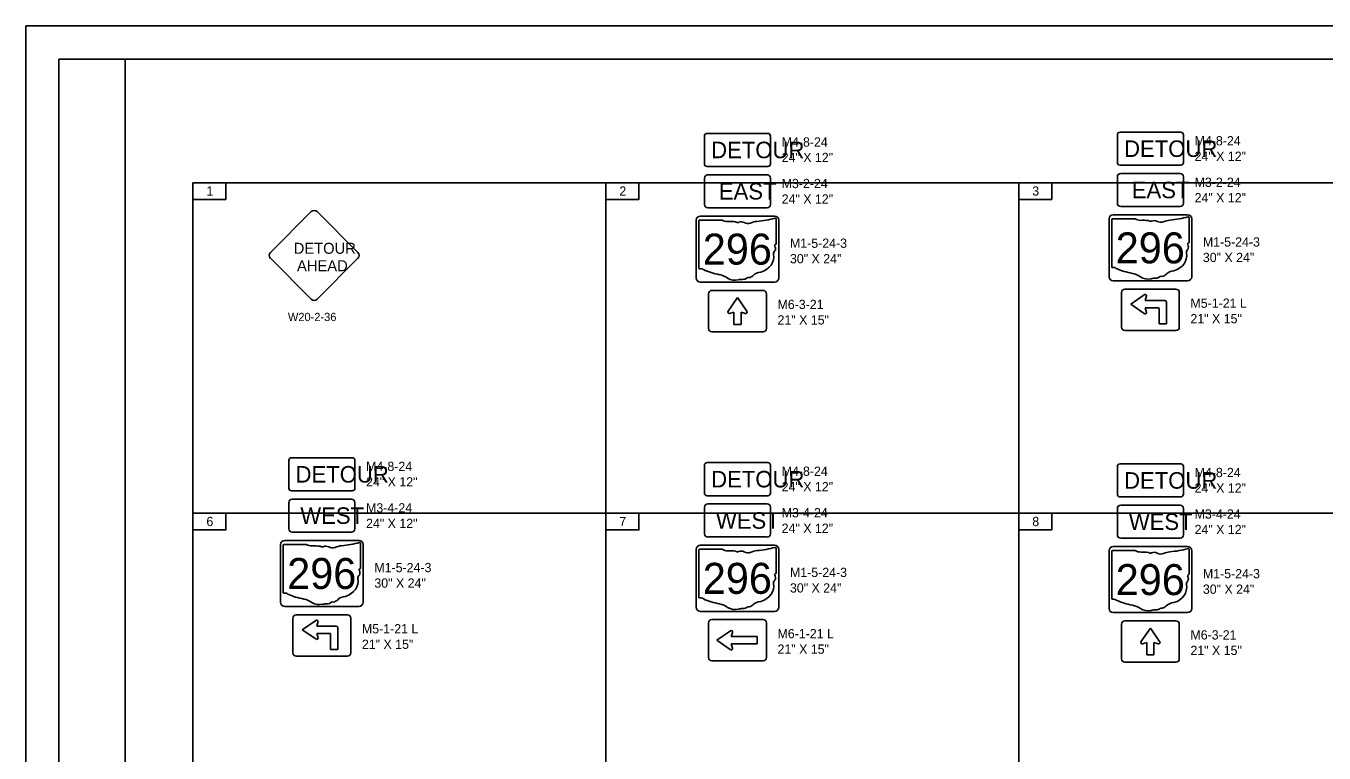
# Model space of a CAD drawing. Extents: x 0 to 715, y 0 to 440.
# Drawn here: x 0 to 393, y 220 to 440 of the extents above; entities that cross this region are included whole.
import ezdxf

# ---------------------------------------------------------------- set-up
doc = ezdxf.new("R2010")
doc.units = 0
for name, color, linetype in [('SC_Scratch1', 7, 'Continuous'), ('SH_Border', 7, 'Continuous'), ('SH_Cut_Line', 7, 'Continuous'), ('SH_Text', 7, 'Continuous'), ('SN_P_Signs', 7, 'Continuous'), ('SN_P_Text', 7, 'Continuous')]:
    doc.layers.add(name, color=color, linetype=linetype)

msp = doc.modelspace()

# ---------------------------------------------------------------- linework, layer by layer
at = {"layer": 'SC_Scratch1'}
for p, q in [((50.54, 392.53), (50.54, 292.53)), ((50.54, 392.53), (225.54, 392.53)), ((175.54, 392.53), (175.54, 292.53)), ((225.54, 392.53), (375.54, 392.53)), ((300.54, 392.53), (300.54, 292.53)), ((375.54, 392.53), (550.54, 392.53)), ((50.54, 292.53), (50.54, 192.53)), ((50.54, 292.53), (225.54, 292.53)), ((175.54, 292.53), (175.54, 192.53)), ((225.54, 292.53), (375.54, 292.53)), ((300.54, 292.53), (300.54, 192.53)), ((375.54, 292.53), (550.54, 292.53))]:
    msp.add_line(p, q, dxfattribs=at)
at = {"layer": 'SH_Border'}
for points in [[(10, 430), (30, 430), (30, 10), (10, 10)], [(30, 430), (670, 430), (670, 10), (30, 10)]]:
    msp.add_lwpolyline(points, close=True, dxfattribs=at)
at = {"layer": 'SH_Cut_Line'}
msp.add_lwpolyline([(0, 0), (680, 0), (680, 440), (0, 440)], close=True, dxfattribs=at)
at = {"layer": 'SH_Text'}
for points in [[(50.54, 392.53), (60.54, 392.53), (60.54, 387.53), (50.54, 387.53)], [(175.54, 392.53), (185.54, 392.53), (185.54, 387.53), (175.54, 387.53)], [(300.54, 392.53), (310.54, 392.53), (310.54, 387.53), (300.54, 387.53)], [(50.54, 292.53), (60.54, 292.53), (60.54, 287.53), (50.54, 287.53)], [(175.54, 292.53), (185.54, 292.53), (185.54, 287.53), (175.54, 287.53)], [(300.54, 292.53), (310.54, 292.53), (310.54, 287.53), (300.54, 287.53)]]:
    msp.add_lwpolyline(points, close=True, dxfattribs=at)
at = {"layer": 'SN_P_Signs'}
for p, q in [((205.39, 385.99), (205.39, 393.99)), ((206.39, 394.99), (224.39, 394.99)), ((225.39, 393.99), (225.39, 385.99)), ((330.39, 386.37), (330.39, 394.37)), ((331.39, 395.37), (349.39, 395.37)), ((350.39, 394.37), (350.39, 386.37)), ((349.39, 385.37), (331.39, 385.37)), ((210.76, 381.26), (203.9, 381.26)), ((224.39, 384.99), (206.39, 384.99)), ((227.11, 374.17), (227.11, 381.61)), ((328.67, 381.39), (328.67, 367.16)), ((335.76, 381.64), (328.9, 381.64)), ((352.11, 374.55), (352.11, 381.99)), ((203.67, 381.02), (203.67, 366.79)), ((227.1, 374.17), (227.11, 374.17)), ((352.1, 374.55), (352.11, 374.55)), ((206.64, 348.49), (206.64, 358.99)), ((207.64, 359.99), (223.14, 359.99)), ((212.54, 353.66), (215.39, 357.8)), ((215.39, 357.8), (218.18, 353.72)), ((224.14, 358.99), (224.14, 348.49)), ((331.64, 348.87), (331.64, 359.37)), ((332.64, 360.37), (348.14, 360.37)), ((338.53, 358.63), (334.45, 355.83)), ((338.83, 356.93), (339.24, 358.33)), ((349.14, 359.37), (349.14, 348.87)), ((334.45, 355.83), (338.53, 353.04)), ((344.76, 356.93), (338.83, 356.93)), ((339.24, 353.33), (338.83, 354.74)), ((338.83, 354.74), (342.73, 354.74)), ((343.04, 354.43), (343.04, 349.9)), ((344.76, 356.93), (344.76, 356.93)), ((345.23, 349.9), (345.23, 356.46)), ((214.29, 353.42), (213.01, 353.03)), ((214.29, 349.67), (214.29, 353.42)), ((217.76, 353.03), (216.48, 353.42)), ((216.48, 353.42), (216.48, 349.67)), ((343.04, 349.9), (345.23, 349.9)), ((343.04, 349.9), (345.23, 349.9)), ((223.14, 347.49), (207.64, 347.49)), ((216.48, 349.67), (214.29, 349.67)), ((348.14, 347.87), (332.64, 347.87)), ((79.58, 287.84), (79.58, 295.84)), ((80.58, 296.84), (98.58, 296.84)), ((99.58, 295.84), (99.58, 287.84)), ((206.39, 295.37), (224.39, 295.37)), ((331.39, 294.99), (349.39, 294.99)), ((205.39, 286.37), (205.39, 294.37)), ((225.39, 294.37), (225.39, 286.37)), ((330.39, 285.99), (330.39, 293.99)), ((350.39, 293.99), (350.39, 285.99)), ((84.95, 283.11), (78.09, 283.11)), ((98.58, 286.84), (80.58, 286.84)), ((101.29, 276.02), (101.29, 283.46)), ((224.39, 285.37), (206.39, 285.37)), ((349.39, 284.99), (331.39, 284.99)), ((77.86, 282.87), (77.86, 268.64)), ((203.67, 281.39), (203.67, 267.16)), ((210.76, 281.64), (203.9, 281.64)), ((227.11, 274.55), (227.11, 281.99)), ((328.67, 281.02), (328.67, 266.79)), ((335.76, 281.26), (328.9, 281.26)), ((352.11, 274.17), (352.11, 281.61)), ((101.29, 276.02), (101.29, 276.02)), ((227.1, 274.55), (227.11, 274.55)), ((352.1, 274.17), (352.11, 274.17)), ((80.83, 250.34), (80.83, 260.84)), ((81.83, 261.84), (97.33, 261.84)), ((87.72, 260.1), (83.64, 257.31)), ((88.01, 258.4), (88.43, 259.81)), ((98.33, 260.84), (98.33, 250.34)), ((206.64, 259.37), (206.64, 248.87)), ((223.14, 260.37), (207.64, 260.37)), ((223.14, 260.37), (223.14, 260.37)), ((224.14, 248.87), (224.14, 259.37)), ((332.64, 259.99), (348.14, 259.99)), ((83.64, 257.31), (87.72, 254.51)), ((93.95, 258.4), (88.01, 258.4)), ((88.43, 254.81), (88.01, 256.21)), ((88.01, 256.21), (91.92, 256.21)), ((92.23, 255.9), (92.23, 251.37)), ((93.95, 258.4), (93.95, 258.4)), ((94.42, 251.37), (94.42, 257.93)), ((209.14, 254.12), (213.28, 256.96)), ((213.91, 256.49), (213.51, 255.21)), ((331.64, 248.49), (331.64, 258.99)), ((337.54, 253.66), (340.39, 257.8)), ((340.39, 257.8), (343.18, 253.72)), ((349.14, 258.99), (349.14, 248.49)), ((213.22, 251.32), (209.14, 254.12)), ((213.51, 255.21), (221.32, 255.21)), ((221.32, 253.02), (213.51, 253.02)), ((213.51, 253.02), (213.91, 251.74)), ((221.32, 255.21), (221.32, 253.02)), ((339.29, 253.42), (338.01, 253.03)), ((339.29, 249.67), (339.29, 253.42)), ((342.76, 253.03), (341.48, 253.42)), ((341.48, 253.42), (341.48, 249.67)), ((97.33, 249.34), (81.83, 249.34)), ((92.23, 251.37), (94.42, 251.37)), ((92.23, 251.37), (94.42, 251.37)), ((207.64, 247.87), (223.14, 247.87)), ((341.48, 249.67), (339.29, 249.67)), ((348.14, 247.49), (332.64, 247.49))]:
    msp.add_line(p, q, dxfattribs=at)
for points in [[(205.39, 406.69), (205.39, 398.29)], [(224.59, 407.49), (206.19, 407.49)], [(225.39, 398.29), (225.39, 406.69)], [(330.39, 407.07), (330.39, 398.67)], [(349.59, 407.87), (331.19, 407.87)], [(350.39, 398.67), (350.39, 407.07)], [(206.19, 397.49), (224.59, 397.49)], [(331.19, 397.87), (349.59, 397.87)], [(73.99, 371.46), (86.37, 383.83)], [(88.14, 383.83), (100.51, 371.46)], [(202.89, 363.74), (202.89, 381.24)], [(204.14, 382.49), (226.64, 382.49)], [(227.89, 381.24), (227.89, 363.74)], [(327.89, 364.12), (327.89, 381.62)], [(329.14, 382.87), (351.64, 382.87)], [(352.89, 381.62), (352.89, 364.12)], [(86.37, 357.32), (73.99, 369.69)], [(100.51, 369.69), (88.14, 357.32)], [(226.64, 362.49), (204.14, 362.49)], [(351.64, 362.87), (329.14, 362.87)], [(79.58, 308.54), (79.58, 300.14)], [(98.78, 309.34), (80.38, 309.34)], [(99.58, 300.14), (99.58, 308.54)], [(205.39, 307.07), (205.39, 298.67)], [(224.59, 307.87), (206.19, 307.87)], [(225.39, 298.67), (225.39, 307.07)], [(330.39, 306.69), (330.39, 298.29)], [(349.59, 307.49), (331.19, 307.49)], [(350.39, 298.29), (350.39, 306.69)], [(80.38, 299.34), (98.78, 299.34)], [(206.19, 297.87), (224.59, 297.87)], [(331.19, 297.49), (349.59, 297.49)], [(77.08, 265.59), (77.08, 283.09)], [(78.33, 284.34), (100.83, 284.34)], [(102.08, 283.09), (102.08, 265.59)], [(202.89, 264.12), (202.89, 281.62)], [(204.14, 282.87), (226.64, 282.87)], [(227.89, 281.62), (227.89, 264.12)], [(327.89, 263.74), (327.89, 281.24)], [(329.14, 282.49), (351.64, 282.49)], [(352.89, 281.24), (352.89, 263.74)], [(100.83, 264.34), (78.33, 264.34)], [(226.64, 262.87), (204.14, 262.87)], [(351.64, 262.49), (329.14, 262.49)]]:
    msp.add_lwpolyline(points, dxfattribs=at)
for centre, radius, start, end in [((206.19, 406.69), 0.8, 90, 180), ((224.59, 406.69), 0.8, 0, 90), ((331.19, 407.07), 0.8, 90, 180), ((349.59, 407.07), 0.8, 0, 90), ((206.19, 398.29), 0.8, 180, 270), ((224.59, 398.29), 0.8, 270, 0), ((331.19, 398.67), 0.8, 180, 270), ((349.59, 398.67), 0.8, 270, 0), ((206.39, 393.99), 1, 90, 180), ((224.39, 393.99), 1, 0, 90), ((331.39, 394.36), 1, 90, 180), ((349.39, 394.36), 1, 0, 90), ((206.39, 385.99), 1, 180, 270), ((224.39, 385.99), 1, 270, 0), ((331.39, 386.36), 1, 180, 270), ((349.39, 386.36), 1, 270, 0), ((87.25, 382.95), 1.25, 45, 135), ((204.14, 381.24), 1.25, 90, 180), ((226.64, 381.24), 1.25, 0, 90), ((329.14, 381.62), 1.25, 90, 180), ((351.64, 381.62), 1.25, 0, 90), ((74.88, 370.57), 1.25, 135, 225), ((99.63, 370.57), 1.25, 315, 45), ((204.14, 363.74), 1.25, 180, 270), ((226.64, 363.74), 1.25, 270, 0), ((329.14, 364.12), 1.25, 180, 270), ((351.64, 364.12), 1.25, 270, 0), ((207.64, 358.99), 1, 90, 180), ((223.14, 358.99), 1, 0, 90), ((332.64, 359.37), 1, 90, 180), ((338.83, 358.33), 0.417, 0.0017, 134.9999), ((348.14, 359.37), 1, 0, 90), ((87.25, 358.2), 1.25, 225, 315), ((212.89, 353.43), 0.417, 145.4112, 287.2046), ((217.89, 353.43), 0.417, 252.7954, 45.0096), ((342.73, 354.43), 0.312, 0, 90), ((344.76, 356.46), 0.469, 0, 90), ((338.83, 353.33), 0.417, 225.0001, 0.0017), ((207.64, 348.49), 1, 180, 270), ((223.14, 348.49), 1, 270, 0), ((332.64, 348.87), 1, 180, 270), ((348.14, 348.87), 1, 270, 360), ((80.38, 308.54), 0.8, 90, 180), ((98.78, 308.54), 0.8, 0, 90), ((206.19, 307.07), 0.8, 90, 180), ((224.59, 307.07), 0.8, 0, 90), ((331.19, 306.69), 0.8, 90, 180), ((349.59, 306.69), 0.8, 0, 90), ((80.38, 300.14), 0.8, 180, 270), ((98.78, 300.14), 0.8, 270, 0), ((206.19, 298.67), 0.8, 180, 270), ((224.59, 298.67), 0.8, 270, 0), ((80.58, 295.84), 1, 90, 180), ((98.58, 295.84), 1, 0, 90), ((206.39, 294.36), 1, 90, 180), ((224.39, 294.36), 1, 0, 90), ((331.19, 298.29), 0.8, 180, 270), ((331.39, 293.99), 1, 90, 180), ((349.39, 293.99), 1, 0, 90), ((349.59, 298.29), 0.8, 270, 0), ((80.58, 287.84), 1, 180, 270), ((98.58, 287.84), 1, 270, 0), ((78.33, 283.09), 1.25, 90, 180), ((100.83, 283.09), 1.25, 0, 90), ((206.39, 286.36), 1, 180, 270), ((224.39, 286.36), 1, 270, 0), ((331.39, 285.99), 1, 180, 270), ((349.39, 285.99), 1, 270, 0), ((204.14, 281.62), 1.25, 90, 180), ((226.64, 281.62), 1.25, 0, 90), ((329.14, 281.24), 1.25, 90, 180), ((351.64, 281.24), 1.25, 0, 90), ((78.33, 265.59), 1.25, 180, 270), ((100.83, 265.59), 1.25, 270, 0), ((204.14, 264.12), 1.25, 180, 270), ((226.64, 264.12), 1.25, 270, 0), ((329.14, 263.74), 1.25, 180, 270), ((351.64, 263.74), 1.25, 270, 0), ((81.83, 260.84), 1, 90, 180), ((88.01, 259.81), 0.417, 0.0017, 134.9999), ((97.33, 260.84), 1, 0, 90), ((207.64, 259.37), 1, 90, 180), ((223.14, 259.37), 1, 0, 90), ((332.64, 258.99), 1, 90, 180), ((348.14, 258.99), 1, 0, 90), ((91.92, 255.9), 0.312, 0, 90), ((93.95, 257.93), 0.469, 0, 90), ((213.51, 256.62), 0.417, 342.7954, 124.5888), ((88.01, 254.81), 0.417, 225.0001, 0.0017), ((213.51, 251.62), 0.417, 224.9904, 17.2046), ((337.89, 253.43), 0.417, 145.4112, 287.2046), ((342.89, 253.43), 0.417, 252.7954, 45.0096), ((81.83, 250.34), 1, 180, 270), ((97.33, 250.34), 1, 270, 360), ((207.64, 248.87), 1, 180, 270), ((223.14, 248.87), 1, 270, 0), ((332.64, 248.49), 1, 180, 270), ((348.14, 248.49), 1, 270, 0)]:
    msp.add_arc(centre, radius, start, end, dxfattribs=at)
for centre, major_axis, start_param, end_param in [((203.94, 381.05), (0.272, 0), 1.712693, 3.28349), ((212.4, 382.91), (2.63, 0), 4.042523, 4.731795), ((218.76, 400.66), (24.85, 0), 4.814394, 5.042369), ((226.85, 381.64), (0.261, 0), 6.141152, 7.989035), ((328.94, 381.42), (0.272, 0), 1.712693, 3.28349), ((337.4, 383.29), (2.63, 0), 4.042523, 4.731795), ((338.27, 373.65), (9.45, 0), 1.404758, 1.657858), ((341.53, 379.85), (1.58, 0), 0.950623, 2.079405), ((346.93, 377.29), (5, 0), 1.699011, 2.107814), ((343.76, 401.04), (24.85, 0), 4.814394, 5.042369), ((351.85, 382.02), (0.261, 0), 6.141152, 7.989035), ((213.27, 373.27), (9.45, 0), 1.404758, 1.657858), ((215.42, 381.12), (0.76, 0), 3.836095, 5.185415), ((216.53, 379.48), (1.58, 0), 0.950623, 2.079405), ((218.57, 381.73), (1.9, 0), 4.081561, 5.145723), ((221.93, 376.91), (5, 0), 1.699011, 2.107814), ((340.42, 381.5), (0.76, 0), 3.836095, 5.185415), ((343.57, 382.11), (1.9, 0), 4.081561, 5.145723), ((227.05, 373.62), (0.404, 0), 1.883978, 3.671073), ((224.48, 372.68), (2.42, 0), 5.934695, 6.695948), ((226.83, 374.14), (0.279, 0), 5.05454, 6.418171), ((352.05, 374), (0.404, 0), 1.883978, 3.671073), ((349.48, 373.06), (2.42, 0), 5.934695, 6.695948), ((351.83, 374.52), (0.279, 0), 5.05454, 6.418171), ((220.15, 370.11), (6.22, 0), 5.101752, 6.440018), ((228.04, 371.05), (1.76, 0), 2.387724, 3.262537), ((345.15, 370.48), (6.22, 0), 5.101752, 6.440018), ((353.04, 371.43), (1.76, 0), 2.387724, 3.262537), ((203.94, 366.75), (0.274, 0), 3.00124, 4.508301), ((203.98, 368.21), (2.09, 0), 4.665946, 4.897461), ((204.41, 365.96), (0.754, 0), 0.519207, 1.627899), ((213.93, 378.75), (17.95, 0), 4.195997, 4.488961), ((222.77, 362.79), (3.4, 0), 1.647645, 2.488434), ((328.94, 367.13), (0.274, 0), 3.00124, 4.508301), ((328.98, 368.59), (2.09, 0), 4.665946, 4.897461), ((329.41, 366.34), (0.754, 0), 0.519207, 1.627899), ((338.93, 379.13), (17.95, 0), 4.195997, 4.488961), ((347.77, 363.17), (3.4, 0), 1.647645, 2.488434), ((208.57, 360.39), (5.62, 0), 0.823519, 1.323587), ((214.65, 365.89), (3.56, 0), 4.026481, 4.996735), ((216.71, 360.97), (2.93, 0), 1.495662, 1.94098), ((216.97, 364.83), (1.9, 0), 4.691044, 5.507374), ((218.69, 363.45), (0.535, 0), 1.147584, 2.315152), ((218.46, 365.41), (2.01, 0), 4.937069, 5.64225), ((333.57, 360.77), (5.62, 0), 0.823519, 1.323587), ((339.65, 366.27), (3.56, 0), 4.026481, 4.996735), ((341.71, 361.35), (2.93, 0), 1.495662, 1.94098), ((341.97, 365.21), (1.9, 0), 4.691044, 5.507374), ((343.69, 363.83), (0.535, 0), 1.147584, 2.315152), ((343.46, 365.78), (2.01, 0), 4.937069, 5.64225), ((78.13, 282.9), (0.272, 0), 1.712693, 3.28349), ((86.59, 284.76), (2.63, 0), 4.042523, 4.731795), ((92.95, 302.51), (24.85, 0), 4.814394, 5.042369), ((101.03, 283.49), (0.261, 0), 6.141152, 7.989035), ((87.46, 275.12), (9.45, 0), 1.404758, 1.657858), ((89.61, 282.97), (0.76, 0), 3.836095, 5.185415), ((90.72, 281.33), (1.58, 0), 0.950623, 2.079405), ((92.76, 283.58), (1.9, 0), 4.081561, 5.145723), ((96.12, 278.76), (5, 0), 1.699011, 2.107814), ((203.94, 281.42), (0.272, 0), 1.712693, 3.28349), ((212.4, 283.29), (2.63, 0), 4.042523, 4.731795), ((213.27, 273.65), (9.45, 0), 1.404758, 1.657858), ((215.42, 281.5), (0.76, 0), 3.836095, 5.185415), ((216.53, 279.85), (1.58, 0), 0.950623, 2.079405), ((218.57, 282.11), (1.9, 0), 4.081561, 5.145723), ((221.93, 277.29), (5, 0), 1.699011, 2.107814), ((218.76, 301.04), (24.85, 0), 4.814394, 5.042369), ((226.85, 282.02), (0.261, 0), 6.141152, 7.989035), ((328.94, 281.05), (0.272, 0), 1.712693, 3.28349), ((337.4, 282.91), (2.63, 0), 4.042523, 4.731795), ((338.27, 273.27), (9.45, 0), 1.404758, 1.657858), ((340.42, 281.12), (0.76, 0), 3.836095, 5.185415), ((341.53, 279.48), (1.58, 0), 0.950623, 2.079405), ((343.57, 281.73), (1.9, 0), 4.081561, 5.145723), ((346.93, 276.91), (5, 0), 1.699011, 2.107814), ((343.76, 300.66), (24.85, 0), 4.814394, 5.042369), ((351.85, 281.64), (0.261, 0), 6.141152, 7.989035), ((101.23, 275.47), (0.404, 0), 1.883978, 3.671073), ((98.66, 274.53), (2.42, 0), 5.934695, 6.695948), ((101.02, 275.99), (0.279, 0), 5.05454, 6.418171), ((94.34, 271.96), (6.22, 0), 5.101752, 6.440018), ((102.23, 272.9), (1.76, 0), 2.387724, 3.262537), ((220.15, 270.48), (6.22, 0), 5.101752, 6.440018), ((228.04, 271.43), (1.76, 0), 2.387724, 3.262537), ((227.05, 274), (0.404, 0), 1.883978, 3.671073), ((224.48, 273.06), (2.42, 0), 5.934695, 6.695948), ((226.83, 274.52), (0.279, 0), 5.05454, 6.418171), ((353.04, 271.05), (1.76, 0), 2.387724, 3.262537), ((352.05, 273.62), (0.404, 0), 1.883978, 3.671073), ((349.48, 272.68), (2.42, 0), 5.934695, 6.695948), ((351.83, 274.14), (0.279, 0), 5.05454, 6.418171), ((78.13, 268.6), (0.274, 0), 3.00124, 4.508301), ((78.17, 270.06), (2.09, 0), 4.665946, 4.897461), ((78.6, 267.81), (0.754, 0), 0.519207, 1.627899), ((88.11, 280.6), (17.95, 0), 4.195997, 4.488961), ((96.96, 264.64), (3.4, 0), 1.647645, 2.488434), ((345.15, 270.11), (6.22, 0), 5.101752, 6.440018), ((82.76, 262.24), (5.62, 0), 0.823519, 1.323587), ((88.84, 267.74), (3.56, 0), 4.026481, 4.996735), ((90.9, 262.82), (2.93, 0), 1.495662, 1.94098), ((91.16, 266.68), (1.9, 0), 4.691044, 5.507374), ((92.87, 265.3), (0.535, 0), 1.147584, 2.315152), ((92.65, 267.26), (2.01, 0), 4.937069, 5.64225), ((203.94, 267.13), (0.274, 0), 3.00124, 4.508301), ((203.98, 268.59), (2.09, 0), 4.665946, 4.897461), ((204.41, 266.34), (0.754, 0), 0.519207, 1.627899), ((213.93, 279.13), (17.95, 0), 4.195997, 4.488961), ((208.57, 260.77), (5.62, 0), 0.823519, 1.323587), ((214.65, 266.27), (3.56, 0), 4.026481, 4.996735), ((216.71, 261.35), (2.93, 0), 1.495662, 1.94098), ((216.97, 265.21), (1.9, 0), 4.691044, 5.507374), ((218.69, 263.83), (0.535, 0), 1.147584, 2.315152), ((218.46, 265.78), (2.01, 0), 4.937069, 5.64225), ((222.77, 263.17), (3.4, 0), 1.647645, 2.488434), ((328.94, 266.75), (0.274, 0), 3.00124, 4.508301), ((328.98, 268.21), (2.09, 0), 4.665946, 4.897461), ((329.41, 265.96), (0.754, 0), 0.519207, 1.627899), ((338.93, 278.75), (17.95, 0), 4.195997, 4.488961), ((333.57, 260.39), (5.62, 0), 0.823519, 1.323587), ((339.65, 265.89), (3.56, 0), 4.026481, 4.996735), ((341.71, 260.97), (2.93, 0), 1.495662, 1.94098), ((341.97, 264.83), (1.9, 0), 4.691044, 5.507374), ((343.69, 263.45), (0.535, 0), 1.147584, 2.315152), ((343.46, 265.41), (2.01, 0), 4.937069, 5.64225), ((347.77, 262.79), (3.4, 0), 1.647645, 2.488434)]:
    msp.add_ellipse(centre, major_axis=major_axis, ratio=0.8, start_param=start_param, end_param=end_param, dxfattribs=at)

# ---------------------------------------------------------------- texts
at = {"layer": 'SH_Text'}
for s, p in [('1', (54.63, 388.66)), ('2', (179.63, 388.66)), ('3', (304.63, 388.66)), ('6', (54.63, 288.66)), ('7', (179.63, 288.66)), ('8', (304.63, 288.66))]:
    msp.add_text(s, height=2.8, dxfattribs=at).set_placement(p)
at = {"layer": 'SN_P_Signs'}
for s, height, p in [('DETOUR', 5, (207.42, 399.99)), ('DETOUR', 5, (332.42, 400.37)), ('EAST', 5, (209.75, 387.49)), ('EAST', 5, (334.75, 387.87)), ('296', 9.375, (204.89, 367.79)), ('296', 9.375, (329.89, 368.17)), ('DETOUR', 3.333, (81.05, 371.06)), ('AHEAD', 3.333, (82.05, 365.78)), ('DETOUR', 5, (81.61, 301.84)), ('DETOUR', 5, (207.42, 300.37)), ('DETOUR', 5, (332.42, 299.99)), ('WEST', 5, (83.05, 289.34)), ('WEST', 5, (208.86, 287.87)), ('WEST', 5, (333.86, 287.49)), ('296', 9.375, (79.08, 269.64)), ('296', 9.375, (204.89, 268.17)), ('296', 9.375, (329.89, 267.79))]:
    msp.add_text(s, height=height, dxfattribs=at).set_placement(p)
at = {"layer": 'SN_P_Text'}
for s, height, p in [('M4-8-24', 2.8, (228.77, 403.49)), ('M4-8-24', 2.8, (353.77, 403.87)), ('24" X 12"', 2.8, (228.77, 398.8)), ('24" X 12"', 2.8, (353.77, 399.18)), ('M3-2-24', 2.8, (228.77, 390.93)), ('M3-2-24', 2.8, (353.77, 391.31)), ('24" X 12"', 2.8, (228.77, 386.24)), ('24" X 12"', 2.8, (353.77, 386.62)), ('M1-5-24-3', 2.8, (231.28, 372.87)), ('M1-5-24-3', 2.8, (356.28, 373.25)), ('30" X 24"', 2.8, (231.28, 368.18)), ('30" X 24"', 2.8, (356.28, 368.56)), ('M6-3-21', 2.8, (227.51, 354.35)), ('M5-1-21 L', 2.8, (352.51, 354.73)), ('W20-2-36', 2.5, (79.3, 350.7)), ('21" X 15"', 2.8, (227.51, 349.66)), ('21" X 15"', 2.8, (352.51, 350.04)), ('M4-8-24', 2.8, (102.96, 305.34)), ('M4-8-24', 2.8, (228.77, 303.87)), ('24" X 12"', 2.8, (102.96, 300.65)), ('M4-8-24', 2.8, (353.77, 303.49)), ('24" X 12"', 2.8, (228.77, 299.18)), ('24" X 12"', 2.8, (353.77, 298.8)), ('M3-4-24', 2.8, (102.96, 292.78)), ('24" X 12"', 2.8, (102.96, 288.09)), ('M3-4-24', 2.8, (228.77, 291.31)), ('M3-4-24', 2.8, (353.77, 290.93)), ('24" X 12"', 2.8, (228.77, 286.62)), ('24" X 12"', 2.8, (353.77, 286.24)), ('M1-5-24-3', 2.8, (105.47, 274.72)), ('M1-5-24-3', 2.8, (231.28, 273.25)), ('M1-5-24-3', 2.8, (356.28, 272.87)), ('30" X 24"', 2.8, (105.47, 270.03)), ('30" X 24"', 2.8, (231.28, 268.56)), ('30" X 24"', 2.8, (356.28, 268.18)), ('M5-1-21 L', 2.8, (101.7, 256.2)), ('M6-1-21 L', 2.8, (227.51, 254.73)), ('M6-3-21', 2.8, (352.51, 254.35)), ('21" X 15"', 2.8, (101.7, 251.51)), ('21" X 15"', 2.8, (227.51, 250.04)), ('21" X 15"', 2.8, (352.51, 249.66))]:
    msp.add_text(s, height=height, dxfattribs=at).set_placement(p)

doc.saveas('drawing.dxf')
